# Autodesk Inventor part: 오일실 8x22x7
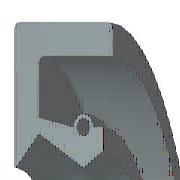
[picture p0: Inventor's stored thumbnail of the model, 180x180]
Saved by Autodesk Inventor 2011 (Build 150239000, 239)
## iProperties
IsCustomPart: 1
Company: 한국ATC센터
Created: 2014-07
Part Number: 오일실 8x22x7
Material: 고무
Description: 오일-실
Document SubType Name: Modeling
Standard: KS B 2804
Designer: KYOUNG IL JANG
Standards Organization: KS
Language: ko-KR
Size Designation: D - 8 22 7
Categories: <MemberInstance><Categories><Category DisplayName="샤프트 부품" InternalName="7f7aeb1f-a693-4053-b835-cee3144e0d98" Mnemonic="SHFT"><Category DisplayName="실링" Intern
Density: 0.93 g/cm^3
Author: KYOUNG IL JANG
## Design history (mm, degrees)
revolve "본체" stored, may be unused: angle "d17" = 90 deg
revolve "스프링1" stored, may be unused: angle "d18" = 90 deg
body "Solid1"
sketch "스케치1"
  geometry: L1 (0, 11)-(7, 11); L2 (7, 9.25)-(1.75, 9.25); L3 (1.75, 5.75)-(4.9, 4); L4 (4.9, 4)-(0, 4); L5 (0, 0)-(9.586, 0) reference; L6 (4.9, 4)-(6.3, 4.875); L7 (0, 18)-(0, -3) reference; L8 (-1.941, 0)-(11.507, 0) reference; L9 (4.2, 6.1)-(1.75, 6.59); L10 (1.75, 6.59)-(1.75, 9.25); L11 (0, 11)-(0, 4.088); L12 (4.9, 4)-(0, 4); L13 (1.75, 5.75)-(0.152, 4.028); L14 (7, 11)-(7, 9.25); L15 (5.6, 6.1)-(6.3, 6.1); L16 (6.3, 6.1)-(6.3, 4.875); C1 r 0.455 at (4.9, 6.1); A1 r 0.7 centre (4.9, 6.1) between (5.6, 6.1) and (4.2, 6.1); A2 r 0.088 centre (0.088, 4.088) between (0, 4.088) and (0.152, 4.028); 1 further point
  constraints: 28 end point, 5 horizontal alignment, 5 point on line, 4 point on circle, 4 vertical alignment, 3 centre point, 3 tangent, 2 collinear, 2 horizontal, 2 perpendicular, 1 coincident, 1 parallel
  dimensions: "d0" = 22 diameter of L1 L5 (= SD2); "d1" = 1.75 distance of L1.end L2.start (= SD); "d2" = 0.91 diameter of C1 (= SPDI); "d3" = 1.4 diameter of A1 (= SPDA); "d4" = 8 diameter of L3.end L5 (= NND); "d5" = 11.5 diameter of L3.start L5 (= TKDM); "d7" = 13.18 diameter of L9.end L5 (= TKDM + 0.24 x SWDT); "d8" = 1.75 distance between parallel lines of L11 L10 (= SD); "d9" = 4.9 distance from line of L11 C1.centre (= SPDST); "d10" = 12.2 diameter of C1.centre L5 (= HLDM); "d11" = 0.0875 radius of A2 (= 0.25 x LAB); "d12" = 6.3 distance between parallel lines of L11 L16 (= SDI); "d13" = 9.75 diameter of L6.end L5 (= ABDM); "d14" = 7 distance from line of L11 L1.end (= SWDT)
fillet "모깎기1" dims "d6" = 0.3 (= RR)
other parameters: "SD2" = 22 [user parameter; used in 1 equation term], "SWDT" = 7 [user parameter; used in 2 equation terms], "RR" = 0.3 [user parameter; used in 1 equation term], "SD" = 1.75 [user parameter; used in 2 equation terms], "NND" = 8 [user parameter; used in 1 equation term], "SPDA" = 1.4 [user parameter; used in 1 equation term], "SPDI" = 0.91 [user parameter; used in 1 equation term], "TKDM" = 11.5 [user parameter; used in 2 equation terms], "HLDM" = 12.2 [user parameter; used in 1 equation term], "ABDM" = 9.75 [user parameter; used in 1 equation term], "SDI" = 6.3 [user parameter; used in 1 equation term], "SPDST" = 4.9 [user parameter; used in 1 equation term], "LAB" = 0.35 [user parameter; used in 1 equation term], "d15" = 0, "d16" = 0, "d19" = 0
